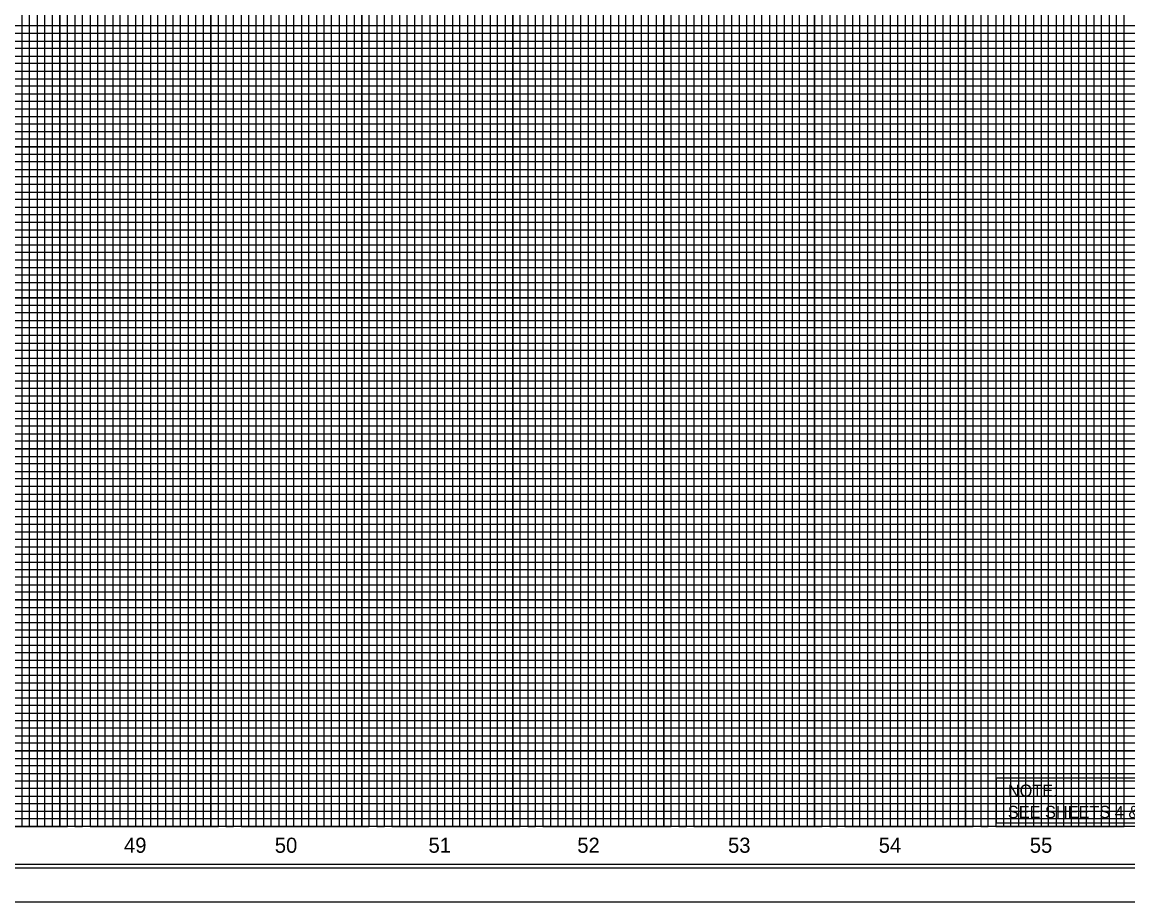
# Model space of a CAD drawing. Extents: x 2195312 to 2197200, y 76953 to 78053.
# Drawn here: x 2196054 to 2196786, y 76953 to 77535 of the extents above; entities that cross this region are included whole.
import ezdxf

# ---------------------------------------------------------------- set-up
doc = ezdxf.new("R2010")
doc.units = 0
for name, color, linetype in [('Exist Structure Minor Culvert Topo', 7, 'Continuous'), ('Old_Level_2', 7, 'Continuous'), ('Old_Level_3', 7, 'Continuous'), ('Prop North Arrow NAD83 for Plan Sheets CELL', 7, 'Continuous'), ('Scratch_Level_0', 7, 'Continuous'), ('Sheet Cutting Line CELL', 7, 'Continuous'), ('Sheet Data Field CELL', 7, 'Continuous'), ('Sheet Plan CELL', 7, 'Continuous'), ('Sheet Plot Border Inside CELL', 7, 'Continuous'), ('Sheet Plot Border Outside CELL', 7, 'Continuous'), ('Sheet Sticker Incomplete CELL', 7, 'Continuous'), ('Sheet Sticker Preliminary CELL', 7, 'Continuous')]:
    doc.layers.add(name, color=color, linetype=linetype)

msp = doc.modelspace()

# ---------------------------------------------------------------- linework, layer by layer
at = {"layer": 'Exist Structure Minor Culvert Topo'}
msp.add_lwpolyline([(2195528.73, 77352.66), (2196928.73, 77352.66), (2196928.73, 77002.66), (2195528.73, 77002.66)], close=True, dxfattribs=at)
at = {"layer": 'Old_Level_2'}
msp.add_lwpolyline([(2196991.23, 78030.21), (2195324.73, 78030.21), (2195324.73, 76975.11), (2196991.23, 76975.11)], close=True, dxfattribs=at)
at = {"layer": 'Old_Level_3'}
msp.add_lwpolyline([(2196699.27, 77034.85), (2196926.09, 77034.85), (2196926.09, 77004.85), (2196699.27, 77004.85)], close=True, dxfattribs=at)
at = {"layer": 'Scratch_Level_0'}
for points in [[(2195528.73, 77702.66), (2196928.73, 77702.66), (2196928.73, 77352.66), (2195528.73, 77352.66)], [(2195528.73, 77702.66), (2196928.73, 77702.66), (2196928.73, 77352.66), (2195528.73, 77352.66)], [(2195528.73, 77402.66), (2196928.73, 77402.66), (2196928.73, 77052.66), (2195528.73, 77052.66)]]:
    msp.add_lwpolyline(points, close=True, dxfattribs=at)
at = {"layer": 'Sheet Cutting Line CELL'}
for points in [[(2196028.73, 77002.66), (2196078.73, 77002.66), (2196078.73, 78027.66)], [(2196128.73, 78027.66), (2196128.73, 77002.66), (2196178.73, 77002.66), (2196178.73, 78027.66)], [(2196228.73, 78027.66), (2196228.73, 77002.66), (2196278.73, 77002.66), (2196278.73, 78027.66)], [(2196328.73, 78027.66), (2196328.73, 77002.66), (2196378.73, 77002.66), (2196378.73, 78027.66)], [(2196428.73, 78027.66), (2196428.73, 77002.66), (2196478.73, 77002.66), (2196478.73, 78027.66)], [(2196528.73, 78027.66), (2196528.73, 77002.66), (2196578.73, 77002.66), (2196578.73, 78027.66)], [(2196628.73, 78027.66), (2196628.73, 77002.66), (2196678.73, 77002.66), (2196678.73, 78027.66)], [(2196728.73, 78027.66), (2196728.73, 77002.66), (2196778.73, 77002.66), (2196778.73, 78027.66)], [(2196978.73, 77452.66), (2195478.73, 77452.66), (2195478.73, 77502.66), (2196978.73, 77502.66)], [(2196978.73, 77352.66), (2195478.73, 77352.66), (2195478.73, 77402.66), (2196978.73, 77402.66)], [(2196978.73, 77252.66), (2195478.73, 77252.66), (2195478.73, 77302.66), (2196978.73, 77302.66)], [(2196978.73, 77152.66), (2195478.73, 77152.66), (2195478.73, 77202.66), (2196978.73, 77202.66)], [(2196978.73, 77052.66), (2195478.73, 77052.66), (2195478.73, 77102.66), (2196978.73, 77102.66)]]:
    msp.add_lwpolyline(points, dxfattribs=at)
at = {"layer": 'Sheet Data Field CELL'}
for points in [[(2196058.73, 77002.66), (2196058.73, 78027.66)], [(2196063.73, 78027.66), (2196063.73, 77002.66), (2196068.73, 77002.66), (2196068.73, 78027.66)], [(2196073.73, 78027.66), (2196073.73, 77002.66), (2196083.73, 77002.66), (2196083.73, 78027.66)], [(2196088.73, 78027.66), (2196088.73, 77002.66), (2196088.73, 77002.66), (2196093.73, 77002.66), (2196093.73, 78027.66)], [(2196098.73, 78027.66), (2196098.73, 77002.66), (2196108.73, 77002.66), (2196108.73, 78027.66)], [(2196113.73, 78027.66), (2196113.73, 77002.66), (2196118.73, 77002.66), (2196118.73, 78027.66)], [(2196123.73, 78027.66), (2196123.73, 77002.66), (2196133.73, 77002.66), (2196133.73, 78027.66)], [(2196138.73, 78027.66), (2196138.73, 77002.66), (2196143.73, 77002.66), (2196143.73, 78027.66)], [(2196148.73, 78027.66), (2196148.73, 77002.66), (2196158.73, 77002.66), (2196158.73, 78027.66)], [(2196163.73, 78027.66), (2196163.73, 77002.66), (2196168.73, 77002.66), (2196168.73, 78027.66)], [(2196173.73, 78027.66), (2196173.73, 77002.66), (2196183.73, 77002.66), (2196183.73, 78027.66)], [(2196188.73, 78027.66), (2196188.73, 77002.66), (2196193.73, 77002.66), (2196193.73, 78027.66)], [(2196198.73, 78027.66), (2196198.73, 77002.66), (2196208.73, 77002.66), (2196208.73, 78027.66)], [(2196213.73, 78027.66), (2196213.73, 77002.66), (2196218.73, 77002.66), (2196218.73, 78027.66)], [(2196223.73, 78027.66), (2196223.73, 77002.66), (2196233.73, 77002.66), (2196233.73, 78027.66)], [(2196238.73, 78027.66), (2196238.73, 77002.66)], [(2196238.73, 77002.66), (2196243.73, 77002.66), (2196243.73, 78027.06)], [(2196248.73, 78027.06), (2196248.73, 77002.66), (2196258.73, 77002.66), (2196258.73, 78027.66)], [(2196263.73, 78027.66), (2196263.73, 77002.66), (2196268.73, 77002.66), (2196268.73, 78027.66)], [(2196273.73, 78027.66), (2196273.73, 77002.66), (2196283.73, 77002.66), (2196283.73, 78027.66)], [(2196288.73, 78027.66), (2196288.73, 77002.66), (2196293.73, 77002.66), (2196293.73, 78027.66)], [(2196298.73, 78027.66), (2196298.73, 77002.66), (2196308.73, 77002.66), (2196308.73, 78027.66)], [(2196313.73, 78027.66), (2196313.73, 77002.66), (2196318.73, 77002.66), (2196318.73, 78027.66)], [(2196323.73, 78027.66), (2196323.73, 77002.66), (2196333.73, 77002.66), (2196333.73, 78027.66)], [(2196338.73, 78027.66), (2196338.73, 77002.66), (2196343.73, 77002.66), (2196343.73, 78027.66)], [(2196348.73, 78027.66), (2196348.73, 77002.66), (2196358.73, 77002.66), (2196358.73, 78027.66)], [(2196363.73, 78027.66), (2196363.73, 77002.66), (2196368.73, 77002.66), (2196368.73, 78027.66)], [(2196373.73, 78027.66), (2196373.73, 77002.66), (2196383.73, 77002.66), (2196383.73, 78027.66)], [(2196388.73, 78027.66), (2196388.73, 77002.66), (2196393.73, 77002.66), (2196393.73, 78027.66)], [(2196398.73, 78027.66), (2196398.73, 77002.66), (2196408.73, 77002.66), (2196408.73, 78027.66)], [(2196413.73, 78027.66), (2196413.73, 77002.66), (2196418.73, 77002.66), (2196418.73, 78027.66)], [(2196423.73, 78027.66), (2196423.73, 77002.66), (2196433.73, 77002.66), (2196433.73, 78027.66)], [(2196438.73, 78027.66), (2196438.73, 77002.66), (2196443.73, 77002.66), (2196443.73, 78027.66)], [(2196448.73, 78027.66), (2196448.73, 77002.66), (2196458.73, 77002.66), (2196458.73, 78027.66)], [(2196463.73, 78027.66), (2196463.73, 77002.66), (2196468.73, 77002.66), (2196468.73, 78027.66)], [(2196473.73, 78027.66), (2196473.73, 77002.66), (2196483.73, 77002.66), (2196483.73, 78027.66)], [(2196488.73, 78027.66), (2196488.73, 77002.66), (2196493.73, 77002.66), (2196493.73, 78027.66)], [(2196498.73, 78027.66), (2196498.73, 77002.66), (2196508.73, 77002.66), (2196508.73, 78027.66)], [(2196513.73, 78027.66), (2196513.73, 77002.66), (2196518.73, 77002.66), (2196518.73, 78027.66)], [(2196523.73, 78027.66), (2196523.73, 77002.66), (2196533.73, 77002.66), (2196533.73, 78027.66)], [(2196538.73, 78027.66), (2196538.73, 77002.66), (2196543.73, 77002.66), (2196543.73, 78027.66)], [(2196548.73, 78027.66), (2196548.73, 77002.66)], [(2196548.73, 77002.66), (2196558.73, 77002.66), (2196558.73, 78027.66)], [(2196563.73, 78027.66), (2196563.73, 77002.66), (2196568.73, 77002.66), (2196568.73, 78027.66)], [(2196573.73, 78027.66), (2196573.73, 77002.66), (2196583.73, 77002.66), (2196583.73, 78027.66)], [(2196588.73, 78027.66), (2196588.73, 77002.66), (2196593.73, 77002.66), (2196593.73, 78027.66)], [(2196598.73, 78027.66), (2196598.73, 77002.66), (2196608.73, 77002.66), (2196608.73, 78027.66)], [(2196613.73, 78027.66), (2196613.73, 77002.66), (2196618.73, 77002.66), (2196618.73, 78027.66)], [(2196623.73, 78027.66), (2196623.73, 77002.66), (2196633.73, 77002.66), (2196633.73, 78027.66)], [(2196638.73, 78027.66), (2196638.73, 77002.66), (2196643.73, 77002.66), (2196643.73, 78027.66)], [(2196648.73, 78027.66), (2196648.73, 77002.66), (2196658.73, 77002.66), (2196658.73, 78027.66)], [(2196663.73, 78027.66), (2196663.73, 77002.66), (2196668.73, 77002.66), (2196668.73, 78027.66)], [(2196673.73, 78027.66), (2196673.73, 77002.66), (2196683.73, 77002.66), (2196683.73, 78027.66)], [(2196688.73, 78027.66), (2196688.73, 77002.66), (2196693.73, 77002.66), (2196693.73, 78027.66)], [(2196698.73, 78027.66), (2196698.73, 77002.66), (2196708.73, 77002.66), (2196708.73, 78027.66)], [(2196713.73, 78027.66), (2196713.73, 77002.66), (2196718.73, 77002.66), (2196718.73, 78027.66)], [(2196723.73, 78027.66), (2196723.73, 77002.66), (2196733.73, 77002.66), (2196733.73, 78027.66)], [(2196738.73, 78027.66), (2196738.73, 77002.66), (2196743.73, 77002.66), (2196743.73, 78027.66)], [(2196748.73, 78027.66), (2196748.73, 77002.66), (2196758.73, 77002.66), (2196758.73, 78027.66)], [(2196763.73, 78027.66), (2196763.73, 77002.66), (2196768.73, 77002.66), (2196768.73, 78027.66)], [(2196773.73, 78027.66), (2196773.73, 77002.66), (2196783.73, 77002.66), (2196783.73, 77866.61)], [(2196928.73, 77532.66), (2195528.73, 77532.66), (2195528.73, 77522.66), (2196928.73, 77522.66)], [(2196928.73, 77517.66), (2195528.73, 77517.66), (2195528.73, 77512.66), (2196928.73, 77512.66)], [(2196928.73, 77507.66), (2195528.73, 77507.66)], [(2195528.73, 77497.66), (2196928.73, 77497.66)], [(2196928.73, 77492.66), (2195528.73, 77492.66), (2195528.73, 77487.66), (2196928.73, 77487.66)], [(2196928.73, 77482.66), (2195528.73, 77482.66), (2195528.73, 77472.66), (2196928.73, 77472.66)], [(2196928.73, 77467.66), (2195528.73, 77467.66), (2195528.73, 77462.66), (2196928.73, 77462.66)], [(2196928.73, 77457.66), (2195528.73, 77457.66), (2195528.73, 77447.66), (2196928.73, 77447.66)], [(2196928.73, 77442.66), (2195528.73, 77442.66), (2195528.73, 77437.66), (2196928.73, 77437.66)], [(2196928.73, 77432.66), (2195528.73, 77432.66), (2195528.73, 77422.66), (2196928.73, 77422.66)], [(2196928.73, 77417.66), (2195528.73, 77417.66), (2195528.73, 77412.66), (2196928.73, 77412.66)], [(2196928.73, 77407.66), (2195528.73, 77407.66), (2195528.73, 77397.66), (2196928.73, 77397.66)], [(2196928.73, 77392.66), (2195528.73, 77392.66), (2195528.73, 77387.66), (2196928.73, 77387.66)], [(2196928.73, 77382.66), (2195528.73, 77382.66), (2195528.73, 77372.66), (2196928.73, 77372.66)], [(2196928.73, 77367.66), (2195528.73, 77367.66), (2195528.73, 77362.66), (2196928.73, 77362.66)], [(2196928.73, 77357.66), (2195528.73, 77357.66), (2195528.73, 77347.66), (2196928.73, 77347.66)], [(2196928.73, 77342.66), (2195528.73, 77342.66), (2195528.73, 77337.66), (2196928.73, 77337.66)], [(2196928.73, 77332.66), (2195528.73, 77332.66), (2195528.73, 77322.66), (2196928.73, 77322.66)], [(2196928.73, 77317.66), (2195528.73, 77317.66), (2195528.73, 77312.66), (2196928.73, 77312.66)], [(2196928.73, 77307.66), (2195528.73, 77307.66), (2195528.73, 77297.66), (2196928.73, 77297.66)], [(2196928.73, 77292.66), (2195528.73, 77292.66), (2195528.73, 77287.66), (2196928.73, 77287.66)], [(2196928.73, 77282.66), (2195528.73, 77282.66), (2195528.73, 77272.66), (2196928.73, 77272.66)], [(2196928.73, 77267.66), (2195528.73, 77267.66), (2195528.73, 77262.66), (2196928.73, 77262.66)], [(2196928.73, 77257.66), (2195528.73, 77257.66), (2195528.73, 77247.66), (2196928.73, 77247.66)], [(2196928.73, 77242.66), (2195528.73, 77242.66), (2195528.73, 77237.66), (2196928.73, 77237.66)], [(2196928.73, 77232.66), (2195528.73, 77232.66), (2195528.73, 77222.66), (2196928.73, 77222.66)], [(2196928.73, 77217.66), (2195528.73, 77217.66), (2195528.73, 77212.66), (2196928.73, 77212.66)], [(2196928.73, 77207.66), (2195528.73, 77207.66)], [(2195528.73, 77197.66), (2196928.73, 77197.66)], [(2196928.73, 77192.66), (2195528.73, 77192.66), (2195528.73, 77187.66), (2196928.73, 77187.66)], [(2196928.73, 77182.66), (2195528.73, 77182.66)], [(2195528.73, 77172.66), (2196928.73, 77172.66)], [(2196928.73, 77167.66), (2195528.73, 77167.66), (2195528.73, 77162.66), (2196928.73, 77162.66)], [(2196928.73, 77157.66), (2195528.73, 77157.66), (2195528.73, 77147.66), (2196928.73, 77147.66)], [(2196928.73, 77142.66), (2195528.73, 77142.66), (2195528.73, 77137.66), (2196928.73, 77137.66)], [(2196928.73, 77132.66), (2195528.73, 77132.66), (2195528.73, 77122.66), (2196928.73, 77122.66)], [(2196928.73, 77117.66), (2195528.73, 77117.66), (2195528.73, 77112.66), (2196928.73, 77112.66)], [(2196928.73, 77107.66), (2195528.73, 77107.66), (2195528.73, 77097.66), (2196928.73, 77097.66)], [(2196928.73, 77092.66), (2195528.73, 77092.66), (2195528.73, 77087.66), (2196928.73, 77087.66)], [(2196928.73, 77082.66), (2195528.73, 77082.66), (2195528.73, 77072.66), (2196928.73, 77072.66)], [(2196928.73, 77067.66), (2195528.73, 77067.66), (2195528.73, 77062.66), (2196928.73, 77062.66)], [(2196928.73, 77057.66), (2195528.73, 77057.66), (2195528.73, 77047.66), (2196928.73, 77047.66)], [(2196928.73, 77042.66), (2195528.73, 77042.66), (2195528.73, 77037.66), (2196928.73, 77037.66)], [(2196928.73, 77032.66), (2195528.73, 77032.66), (2195528.73, 77022.66), (2196928.73, 77022.66)], [(2196928.73, 77017.66), (2195528.73, 77017.66), (2195528.73, 77012.66), (2196928.73, 77012.66)], [(2196928.73, 77007.66), (2195528.73, 77007.66)]]:
    msp.add_lwpolyline(points, dxfattribs=at)
at = {"layer": 'Sheet Plan CELL'}
msp.add_lwpolyline([(2196995.73, 78052.66), (2195311.73, 78052.66), (2195311.73, 76952.66), (2196995.73, 76952.66)], close=True, dxfattribs=at)
at = {"layer": 'Sheet Plot Border Inside CELL'}
for p, q in [((2195478.73, 77352.66), (2196978.73, 77352.66)), ((2196978.73, 77002.66), (2195478.73, 77002.66))]:
    msp.add_line(p, q, dxfattribs=at)
msp.add_lwpolyline([(2196978.73, 78027.66), (2195478.73, 78027.66), (2195478.73, 76977.66), (2196978.73, 76977.66)], close=True, dxfattribs=at)
at = {"layer": 'Sheet Plot Border Outside CELL'}
for points in [[(2196003.73, 77002.66), (2196053.73, 77002.66), (2196053.73, 78027.66)], [(2196103.73, 78027.66), (2196103.73, 77002.66), (2196153.73, 77002.66), (2196153.73, 78027.66)], [(2196203.73, 78027.66), (2196203.73, 77002.66), (2196253.73, 77002.66), (2196253.73, 78027.66)], [(2196303.73, 78027.66), (2196303.73, 77002.66), (2196353.73, 77002.66), (2196353.73, 78027.66)], [(2196403.73, 78027.66), (2196403.73, 77002.66), (2196453.73, 77002.66), (2196453.73, 78027.66)], [(2196503.73, 78027.66), (2196503.73, 77002.66), (2196553.73, 77002.66), (2196553.73, 78027.66)], [(2196603.73, 78027.66), (2196603.73, 77002.66), (2196653.73, 77002.66), (2196653.73, 78027.66)], [(2196703.73, 78027.66), (2196703.73, 77002.66), (2196753.73, 77002.66), (2196753.73, 78027.66)], [(2196978.73, 77527.66), (2195478.73, 77527.66), (2195478.73, 77477.66), (2196978.73, 77477.66)], [(2196978.73, 77427.66), (2195478.73, 77427.66), (2195478.73, 77377.66), (2196978.73, 77377.66)], [(2196978.73, 77327.66), (2195478.73, 77327.66), (2195478.73, 77277.66), (2196978.73, 77277.66)], [(2196978.73, 77227.66), (2195478.73, 77227.66), (2195478.73, 77177.66), (2196978.73, 77177.66)], [(2196978.73, 77127.66), (2195478.73, 77127.66), (2195478.73, 77077.66), (2196978.73, 77077.66)], [(2196978.73, 77027.66), (2195478.73, 77027.66)]]:
    msp.add_lwpolyline(points, dxfattribs=at)
at = {"layer": 'Sheet Sticker Incomplete CELL'}
msp.add_line((2195311.73, 76952.66), (2196995.73, 76952.66), dxfattribs=at)
at = {"layer": 'Sheet Sticker Preliminary CELL'}
for p, q in [((2196078.73, 78027.66), (2196078.73, 77002.66)), ((2196128.73, 78027.66), (2196128.73, 77002.66)), ((2196178.73, 78027.66), (2196178.73, 77002.66)), ((2196228.73, 78027.66), (2196228.73, 77002.66)), ((2196278.73, 78027.66), (2196278.73, 77002.66)), ((2196328.73, 78027.66), (2196328.73, 77002.66)), ((2196378.73, 78027.66), (2196378.73, 77002.66)), ((2196428.73, 78027.66), (2196428.73, 77002.66)), ((2196478.73, 78027.66), (2196478.73, 77002.66)), ((2196528.73, 78027.66), (2196528.73, 77002.66)), ((2196578.73, 78027.66), (2196578.73, 77002.66)), ((2196628.73, 78027.66), (2196628.73, 77002.66)), ((2196678.73, 78027.66), (2196678.73, 77002.66)), ((2196728.73, 78027.66), (2196728.73, 77002.66)), ((2196778.73, 77002.66), (2196778.73, 77890.11)), ((2195478.73, 77502.66), (2196978.73, 77502.66)), ((2195478.73, 77452.66), (2196978.73, 77452.66)), ((2195478.73, 77402.66), (2196978.73, 77402.66)), ((2195478.73, 77352.66), (2196978.73, 77352.66)), ((2195478.73, 77302.66), (2196978.73, 77302.66)), ((2195478.73, 77252.66), (2196978.73, 77252.66)), ((2195478.73, 77202.66), (2196978.73, 77202.66)), ((2195478.73, 77152.66), (2196978.73, 77152.66)), ((2195478.73, 77102.66), (2196978.73, 77102.66)), ((2195478.73, 77052.66), (2196978.73, 77052.66))]:
    msp.add_line(p, q, dxfattribs=at)

# ---------------------------------------------------------------- texts
at = {"layer": 'Exist Structure Minor Culvert Topo'}
for s, height, p in [('NOTE:', 8.077, (2196706.72, 77022.27)), ('SEE SHEETS 4 & 5 FOR -L- PLAN', 8.0769, (2196706.73, 77008.13))]:
    msp.add_text(s, height=height, rotation=0.02303, dxfattribs=at).set_placement(p)
at = {"layer": 'Prop North Arrow NAD83 for Plan Sheets CELL'}
for s, p in [('49', (2196121.24, 76985.16)), ('50', (2196221.12, 76985.16)), ('51', (2196322.95, 76985.16)), ('52', (2196421.5, 76985.16)), ('53', (2196521.34, 76985.16)), ('54', (2196621.18, 76985.16)), ('55', (2196721.27, 76985.16))]:
    msp.add_text(s, height=10, dxfattribs=at).set_placement(p)

doc.saveas('drawing.dxf')
